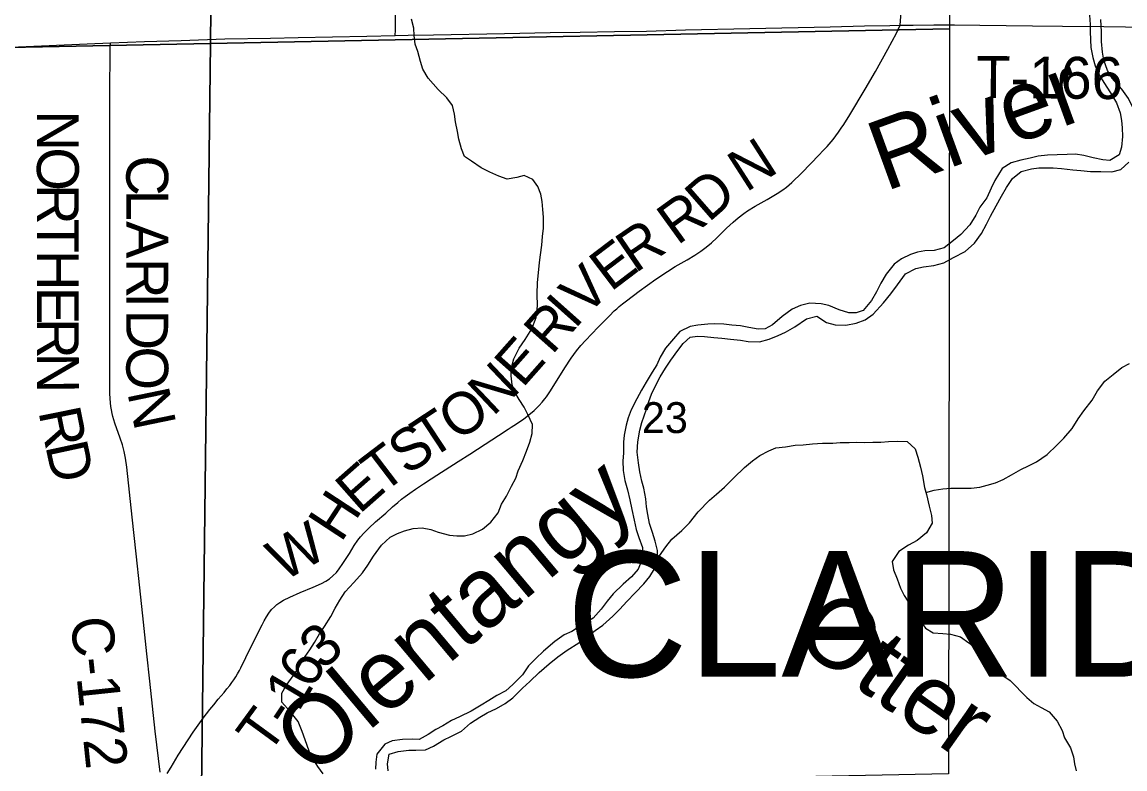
# Model space of a CAD drawing. Extents: x 0 to 45.9, y 0 to 22.
# Drawn here: x 3.224 to 4.718, y 15.719 to 16.732 of the extents above; entities that cross this region are included whole.
import ezdxf

# ---------------------------------------------------------------- set-up
doc = ezdxf.new("R2010")
doc.units = 0
for name, color, linetype in [('GM_X_County_Road', 7, 'Continuous'), ('GM_X_County_Road_Text', 7, 'Continuous'), ('GM_X_Major_River', 7, 'Continuous'), ('GM_X_Major_River_Text', 7, 'Continuous'), ('GM_X_Minor_River', 7, 'Continuous'), ('GM_X_Minor_River_Text', 7, 'Continuous'), ('GM_X_Section', 7, 'Continuous'), ('GM_X_Section_Text', 7, 'Continuous'), ('GM_X_Township_Road', 7, 'Continuous'), ('GM_X_Township_Road_Text', 7, 'Continuous'), ('GM_X_Township_Text', 7, 'Continuous')]:
    doc.layers.add(name, color=color, linetype=linetype)

msp = doc.modelspace()

# ---------------------------------------------------------------- linework, layer by layer
at = {"layer": 'GM_X_County_Road'}
for points in [[(4.4133, 16.7278), (4.4147, 16.7455)], [(3.7293, 16.7137), (3.7467, 16.7141), (3.7809, 16.7148), (3.8772, 16.7165), (3.9393, 16.7177), (3.9797, 16.7185), (4.0263, 16.7194), (4.0698, 16.7199), (4.1226, 16.7214), (4.2096, 16.7232), (4.3184, 16.7256), (4.3649, 16.7269), (4.3991, 16.7275), (4.4133, 16.7278)], [(2.9782, 16.69), (3.0044, 16.6907), (3.0727, 16.6932), (3.1659, 16.6967), (3.2187, 16.6987), (3.3118, 16.7026), (3.3433, 16.7038)], [(3.4107, 15.7149), (3.4041, 15.7704), (3.3966, 15.8383), (3.3927, 15.8754), (3.3881, 15.9186), (3.3833, 15.9649), (3.3782, 16.0112), (3.3728, 16.0606), (3.3655, 16.1286), (3.3638, 16.1408), (3.3619, 16.1499), (3.3596, 16.1588), (3.3567, 16.1677), (3.3496, 16.1882), (3.3481, 16.1928), (3.3469, 16.1972), (3.3459, 16.2015), (3.3448, 16.2063), (3.3441, 16.211), (3.3436, 16.2157), (3.3428, 16.2281), (3.3424, 16.2499), (3.3426, 16.43), (3.3427, 16.5138), (3.3426, 16.5884), (3.3425, 16.635), (3.343, 16.694), (3.3431, 16.6971), (3.3433, 16.7038)], [(3.3433, 16.7038), (3.3895, 16.7057), (3.4391, 16.7072), (3.4982, 16.7091), (3.5603, 16.7104), (3.5976, 16.7112), (3.6908, 16.7129), (3.7293, 16.7137)]]:
    msp.add_lwpolyline(points, dxfattribs=at)
at = {"layer": 'GM_X_Major_River'}
for points in [[(4.6698, 16.7416), (4.6707, 16.7287), (4.6706, 16.7192), (4.6712, 16.7078), (4.6718, 16.6976), (4.6743, 16.6839), (4.6776, 16.6728), (4.6831, 16.6595), (4.6894, 16.6499), (4.6983, 16.6361), (4.7065, 16.6227), (4.7112, 16.609), (4.713, 16.5988), (4.714, 16.5885), (4.7146, 16.5771), (4.7132, 16.5623)], [(4.7299, 16.6133), (4.7225, 16.6282), (4.7136, 16.6412), (4.7005, 16.6562), (4.6942, 16.6665), (4.6894, 16.6803), (4.6873, 16.6913), (4.686, 16.7057), (4.6862, 16.719), (4.6852, 16.7357)], [(4.7132, 16.5623), (4.7101, 16.5521), (4.6974, 16.5443), (4.688, 16.5452), (4.6747, 16.5481), (4.6619, 16.5513), (4.6509, 16.5529), (4.6395, 16.5523), (4.6262, 16.5521), (4.6129, 16.5515), (4.6004, 16.5502), (4.5893, 16.5477), (4.5768, 16.5448), (4.5638, 16.5412), (4.5516, 16.5334), (4.5415, 16.5172), (4.5364, 16.5067), (4.5309, 16.4938), (4.5213, 16.4811), (4.5158, 16.4701), (4.5077, 16.457), (4.4954, 16.4442), (4.4854, 16.436), (4.4727, 16.426), (4.4594, 16.4223), (4.4469, 16.4221), (4.4366, 16.42), (4.4271, 16.4171), (4.4152, 16.4112), (4.4053, 16.4037), (4.3941, 16.3902), (4.3871, 16.3782), (4.3812, 16.3661), (4.3746, 16.3544), (4.3631, 16.3409), (4.3535, 16.338), (4.3437, 16.3378), (4.3308, 16.3421), (4.3168, 16.3476), (4.3063, 16.3501), (4.2911, 16.351), (4.2782, 16.3478), (4.2671, 16.343), (4.2533, 16.3329), (4.2402, 16.3217), (4.2303, 16.3162), (4.2208, 16.3155), (4.2083, 16.318), (4.197, 16.3204), (4.1852, 16.3213), (4.1742, 16.3226), (4.1621, 16.3228), (4.1526, 16.3225), (4.1393, 16.3212), (4.129, 16.3191), (4.1149, 16.3124), (4.106, 16.3027), (4.0952, 16.2899), (4.0882, 16.2779), (4.0835, 16.2673), (4.0773, 16.2572), (4.0692, 16.244), (4.063, 16.2331), (4.0564, 16.221), (4.0489, 16.2063), (4.0446, 16.1954), (4.0422, 16.1855), (4.0394, 16.1719), (4.0385, 16.1625), (4.0387, 16.1477), (4.0378, 16.137), (4.038, 16.1241), (4.0404, 16.1105), (4.0437, 16.0979), (4.0469, 16.0842), (4.0498, 16.0713), (4.053, 16.0568), (4.0555, 16.0439), (4.0591, 16.0332), (4.0642, 16.0195), (4.0648, 16.0062), (4.0582, 15.9903), (4.0493, 15.9798), (4.0382, 15.9701), (4.0247, 15.9566), (4.0162, 15.9469), (4.0081, 15.936), (3.9973, 15.924), (3.9839, 15.9155), (3.9686, 15.9058), (3.9583, 15.901), (3.9453, 15.8921), (3.9299, 15.879), (3.9195, 15.8693), (3.9099, 15.8592), (3.9018, 15.8471), (3.8887, 15.8337), (3.8791, 15.8251), (3.8669, 15.8188), (3.8562, 15.8121), (3.8458, 15.8058)], [(3.8666, 15.8013), (3.8781, 15.808), (3.8885, 15.8158), (3.9015, 15.8289), (3.9115, 15.8379), (3.9242, 15.8503), (3.9377, 15.8618), (3.9495, 15.8715), (3.9622, 15.8805), (3.9779, 15.8905), (4.0001, 15.9069), (4.0105, 15.9143), (4.0239, 15.9267), (4.0335, 15.936), (4.0428, 15.9462), (4.0543, 15.9581), (4.0659, 15.9705), (4.074, 15.9803), (4.0806, 15.9908), (4.0849, 16.0036), (4.0847, 16.0154), (4.0814, 16.0283), (4.0778, 16.0401), (4.0738, 16.052), (4.0713, 16.0645), (4.0696, 16.0748), (4.0686, 16.0858), (4.0661, 16.0999), (4.0632, 16.1094), (4.0607, 16.1223), (4.0586, 16.1345), (4.0569, 16.1489), (4.0578, 16.163), (4.0607, 16.1789), (4.0635, 16.1891), (4.0698, 16.2072), (4.073, 16.2174), (4.0766, 16.2276), (4.0812, 16.2378), (4.0883, 16.2509), (4.0956, 16.263), (4.1026, 16.2735), (4.1119, 16.2867), (4.1192, 16.2964), (4.1288, 16.3046), (4.1387, 16.306), (4.1482, 16.3059), (4.1607, 16.3042), (4.1717, 16.3033), (4.1834, 16.302), (4.1971, 16.3007), (4.2073, 16.299), (4.2228, 16.2984), (4.2358, 16.3021), (4.248, 16.3072), (4.2579, 16.3116), (4.2706, 16.319), (4.2866, 16.3298), (4.3003, 16.3331), (4.3135, 16.3249), (4.3252, 16.3217), (4.3396, 16.3212), (4.3537, 16.3236), (4.3659, 16.3284), (4.3766, 16.3358), (4.3909, 16.3512), (4.4005, 16.3636), (4.4098, 16.3756), (4.4206, 16.3906), (4.4344, 16.398), (4.4451, 16.4002), (4.4587, 16.4022), (4.4724, 16.4055), (4.4854, 16.4129), (4.5015, 16.421), (4.5138, 16.4322), (4.5235, 16.4454), (4.5301, 16.4582), (4.5355, 16.4687), (4.5433, 16.4827), (4.5507, 16.4962), (4.5573, 16.5079), (4.5654, 16.5199), (4.577, 16.5296), (4.591, 16.5332), (4.6013, 16.5346), (4.6207, 16.5344), (4.632, 16.5335), (4.6472, 16.5317), (4.6582, 16.5308), (4.6711, 16.5295), (4.6851, 16.5293), (4.6999, 16.5291), (4.7121, 16.532), (4.7232, 16.5421)], [(3.8458, 15.8058), (3.8321, 15.7976), (3.8164, 15.7899), (3.8053, 15.7851), (3.7938, 15.778), (3.7843, 15.7728), (3.774, 15.7662), (3.7617, 15.7591), (3.7522, 15.7596), (3.7393, 15.7594), (3.7253, 15.7573), (3.7153, 15.7529), (3.7042, 15.7394), (3.7029, 15.7284), (3.7024, 15.7189)], [(3.7198, 15.7168), (3.7188, 15.7263), (3.7212, 15.7392), (3.7334, 15.7432), (3.7475, 15.7449), (3.7573, 15.7448), (3.7703, 15.7453), (3.7809, 15.7501), (3.7951, 15.7587), (3.8047, 15.7635), (3.8188, 15.7705), (3.8311, 15.7813), (3.8437, 15.7895), (3.854, 15.7954), (3.8666, 15.8013)]]:
    msp.add_lwpolyline(points, dxfattribs=at)
at = {"layer": 'GM_X_Minor_River'}
for points in [[(3.7739, 16.6558), (3.7668, 16.6684), (3.7636, 16.6787), (3.76, 16.692), (3.7563, 16.7019), (3.7549, 16.7137), (3.7543, 16.7236), (3.7511, 16.7362)], [(3.6317, 15.7127), (3.6242, 15.7227), (3.6176, 15.7337), (3.6128, 15.7437), (3.6073, 15.7589), (3.6033, 15.77), (3.5978, 15.7837), (3.5869, 15.7971), (3.5757, 15.8098), (3.5755, 15.8219), (3.5813, 15.8325), (3.5887, 15.8426), (3.5972, 15.8547), (3.6042, 15.8671), (3.6135, 15.881), (3.6197, 15.8908), (3.6267, 15.9024), (3.6333, 15.9126), (3.6418, 15.9261), (3.648, 15.9374), (3.6542, 15.948), (3.6616, 15.9593), (3.6732, 15.9724), (3.6847, 15.9851), (3.6921, 15.9956), (3.6998, 16.0077), (3.7107, 16.0227), (3.7222, 16.0336), (3.7321, 16.0387), (3.742, 16.0424), (3.7535, 16.0453), (3.7656, 16.0463), (3.7773, 16.0442), (3.7875, 16.0406), (3.8027, 16.0363), (3.8125, 16.0354), (3.8231, 16.0356), (3.8342, 16.0381), (3.8475, 16.0444), (3.8587, 16.0541), (3.8687, 16.0665), (3.8734, 16.0782), (3.88, 16.0891), (3.8867, 16.1027), (3.8925, 16.1136), (3.896, 16.1234), (3.9019, 16.1377), (3.907, 16.1502), (3.9118, 16.1626), (3.9146, 16.174), (3.9151, 16.1865), (3.9088, 16.1999), (3.9037, 16.2098), (3.897, 16.2205), (3.8914, 16.2301), (3.8878, 16.2404), (3.8864, 16.2525), (3.8866, 16.2639), (3.8898, 16.2756), (3.8972, 16.2899), (3.9053, 16.3016), (3.9142, 16.3163), (3.9201, 16.3317), (3.9222, 16.3473), (3.9217, 16.3632), (3.9219, 16.3788), (3.9232, 16.392), (3.9249, 16.406), (3.9262, 16.4166), (3.9279, 16.4295), (3.9288, 16.4413), (3.9301, 16.4526), (3.9299, 16.4674), (3.9293, 16.4777), (3.9283, 16.4887), (3.9266, 16.4986), (3.9225, 16.5093), (3.9158, 16.5188), (3.9038, 16.5239), (3.8942, 16.5214), (3.8809, 16.5189), (3.8696, 16.5229), (3.8572, 16.5287), (3.8455, 16.5346), (3.8327, 16.5435), (3.8229, 16.55), (3.8189, 16.56), (3.8156, 16.5733), (3.8135, 16.5839), (3.811, 16.5969), (3.8097, 16.6071), (3.8068, 16.6189), (3.7993, 16.6293), (3.7873, 16.6404), (3.7739, 16.6558)], [(4.448, 16.0944), (4.4592, 16.0972), (4.4713, 16.099), (4.482, 16.1), (4.4933, 16.1002), (4.5093, 16.1), (4.5211, 16.1013), (4.5313, 16.1042), (4.5424, 16.1075), (4.5527, 16.1119), (4.5642, 16.1182), (4.5768, 16.1252), (4.5871, 16.1304), (4.5982, 16.1359), (4.6123, 16.1456), (4.6254, 16.1583), (4.635, 16.1677), (4.6462, 16.1812), (4.6544, 16.194), (4.6621, 16.2049), (4.6733, 16.2195), (4.6807, 16.232), (4.6907, 16.2451), (4.7019, 16.2544), (4.7137, 16.2638), (4.7241, 16.2693)], [(4.0849, 16.0044), (4.0872, 16.0085), (4.0958, 16.0206), (4.1039, 16.0311), (4.1177, 16.0426), (4.1281, 16.0531), (4.1397, 16.0681), (4.155, 16.0839), (4.1646, 16.0921), (4.1754, 16.1014), (4.1881, 16.1142), (4.2023, 16.128), (4.2131, 16.1373), (4.2234, 16.1444), (4.2353, 16.1507), (4.2448, 16.1547), (4.2581, 16.1561), (4.271, 16.1582), (4.2817, 16.1588), (4.2946, 16.1601), (4.3082, 16.1611), (4.3219, 16.1613), (4.3322, 16.1619), (4.3443, 16.1621), (4.3546, 16.1624), (4.3648, 16.1622), (4.3762, 16.1625), (4.3872, 16.1623), (4.3974, 16.1633), (4.41, 16.1639), (4.4229, 16.1633), (4.4337, 16.1533), (4.437, 16.1423), (4.441, 16.1286), (4.4435, 16.1168), (4.4463, 16.1012), (4.4488, 16.0913), (4.4524, 16.0757), (4.4557, 16.0631), (4.4567, 16.0525), (4.4489, 16.0397), (4.4362, 16.0292), (4.4244, 16.023), (4.4117, 16.014), (4.4024, 16.0005), (4.4042, 15.9895), (4.409, 15.9773), (4.4137, 15.9643), (4.4189, 15.9544), (4.4338, 15.9314), (4.4408, 15.9199), (4.4475, 15.9104), (4.458, 15.9038), (4.4709, 15.9032), (4.4815, 15.9019), (4.4948, 15.8983), (4.5064, 15.8902), (4.5181, 15.8802), (4.5289, 15.866), (4.5394, 15.856), (4.5495, 15.8479), (4.5623, 15.8394), (4.5847, 15.8163), (4.5945, 15.8082), (4.6043, 15.8028), (4.6152, 15.7966), (4.626, 15.7843), (4.6327, 15.7717), (4.636, 15.7614), (4.6441, 15.748), (4.6481, 15.7358), (4.6495, 15.7263), (4.6517, 15.7168)]]:
    msp.add_lwpolyline(points, dxfattribs=at)
at = {"layer": 'GM_X_Section'}
for points in [[(3.4888, 17.7149), (4.477, 17.7336), (4.4801, 16.7228), (3.479, 16.7029)], [(2.4867, 17.6967), (3.4888, 17.7149), (3.479, 16.7029), (2.4763, 16.6833)], [(3.479, 16.7029), (4.4801, 16.7228), (4.4787, 15.7127), (3.467, 15.6926)], [(3.479, 16.7029), (3.467, 15.6926), (2.4689, 15.6797), (2.4763, 16.6833)]]:
    msp.add_lwpolyline(points, close=True, dxfattribs=at)
at = {"layer": 'GM_X_Township_Road'}
for points in [[(3.7293, 16.7137), (3.7294, 16.7209), (3.7294, 16.724), (3.7294, 16.7613), (3.7293, 16.8016), (3.7299, 16.8638), (3.7302, 16.9259), (3.7302, 16.9974), (3.7299, 17.0471), (3.7297, 17.0875), (3.7299, 17.1279), (3.7299, 17.1714), (3.7296, 17.2087), (3.7298, 17.2304), (3.7301, 17.2646), (3.7305, 17.3205), (3.7309, 17.3734), (3.7319, 17.5101), (3.7325, 17.5753), (3.7326, 17.6219), (3.7331, 17.6717), (3.733, 17.6996), (3.7332, 17.7248)], [(3.9318, 16.2212), (3.9341, 16.2241), (3.9394, 16.2319), (3.9591, 16.2634), (3.9676, 16.2764), (3.9749, 16.2863), (3.9809, 16.2934), (3.9871, 16.3002), (4.0042, 16.3182), (4.0193, 16.3339), (4.0259, 16.3403), (4.0293, 16.3434), (4.0328, 16.3465), (4.0371, 16.35), (4.0425, 16.3543), (4.0598, 16.3674), (4.0825, 16.3836), (4.0979, 16.394), (4.1085, 16.4006), (4.1246, 16.4098), (4.1353, 16.4162), (4.1391, 16.4186), (4.1431, 16.4213), (4.1506, 16.4269), (4.1578, 16.4329), (4.1647, 16.4393), (4.1779, 16.4524), (4.1869, 16.4609), (4.194, 16.4668), (4.2013, 16.4725), (4.2064, 16.4759), (4.217, 16.4824), (4.2332, 16.4915), (4.2467, 16.4994), (4.2545, 16.5045), (4.2595, 16.5083), (4.2665, 16.5145), (4.2799, 16.5275), (4.3037, 16.5521), (4.3087, 16.5574), (4.3143, 16.5635), (4.3224, 16.573), (4.326, 16.5776), (4.3299, 16.5829), (4.3335, 16.588), (4.337, 16.5932), (4.3452, 16.6064), (4.3658, 16.6409), (4.38, 16.6652), (4.3964, 16.6952), (4.4083, 16.7171), (4.4106, 16.7219), (4.4133, 16.7278)], [(4.4133, 16.7278), (4.431, 16.728), (4.459, 16.7284), (4.487, 16.7285), (4.5211, 16.7279), (4.5926, 16.7269), (4.633, 16.7265), (4.689, 16.726), (4.8071, 16.7244), (4.8475, 16.7243), (4.8755, 16.7243), (4.9003, 16.7241), (4.9314, 16.7233), (4.9656, 16.7224), (5.0029, 16.7213), (5.037, 16.72), (5.0743, 16.7181), (5.096, 16.7169), (5.1332, 16.7151), (5.2233, 16.7105), (5.2313, 16.7102)], [(3.8864, 16.1829), (3.8899, 16.1851), (3.9028, 16.1938), (3.9103, 16.1994), (3.9175, 16.2055), (3.9242, 16.212), (3.9283, 16.2167), (3.9318, 16.2212)], [(3.4204, 15.7133), (3.4256, 15.7219), (3.4351, 15.738), (3.4556, 15.7691), (3.4645, 15.7818), (3.4678, 15.7863), (3.4738, 15.7942), (3.478, 15.7998), (3.4834, 15.8064), (3.4895, 15.8138), (3.4973, 15.8231), (3.5011, 15.8278), (3.505, 15.8325), (3.5077, 15.8364), (3.5105, 15.8403), (3.5131, 15.8442), (3.5156, 15.8483), (3.5182, 15.8529), (3.5201, 15.8565), (3.5267, 15.8704), (3.5403, 15.8982), (3.5488, 15.915), (3.5517, 15.9203), (3.5547, 15.9255), (3.558, 15.9306), (3.5618, 15.9354), (3.5655, 15.9394), (3.5689, 15.9422), (3.5729, 15.9452), (3.5779, 15.9482), (3.5864, 15.9525), (3.6006, 15.9588), (3.6181, 15.966), (3.6295, 15.9708), (3.6353, 15.9739), (3.6401, 15.9771), (3.6448, 15.9811), (3.6495, 15.9858), (3.6535, 15.9905), (3.6584, 15.9979), (3.663, 16.0047), (3.6673, 16.0116), (3.6737, 16.0223), (3.6785, 16.0294), (3.6823, 16.034), (3.6868, 16.0391), (3.6935, 16.0458), (3.7023, 16.0543), (3.7164, 16.0664), (3.7256, 16.0747), (3.7326, 16.0808), (3.7379, 16.085), (3.7425, 16.0886), (3.7491, 16.0934), (3.7567, 16.0988), (3.762, 16.1022), (3.7677, 16.1058), (3.778, 16.1128), (3.7858, 16.1178), (3.8146, 16.1362), (3.8302, 16.1463), (3.8511, 16.1598), (3.8693, 16.1716), (3.8821, 16.1801), (3.8864, 16.1829)]]:
    msp.add_lwpolyline(points, dxfattribs=at)

# ---------------------------------------------------------------- texts
at = {"layer": 'GM_X_County_Road_Text'}
for s, height, rotation, p in [('N', 0.0568, 270, (3.2438, 16.6122)), ('O', 0.0568, 269.9981, (3.2438, 16.5622)), ('C', 0.0568, 270, (3.3649, 16.5514)), ('R', 0.0568, 269.9991, (3.2438, 16.5122)), ('L', 0.0568, 269.9985, (3.3649, 16.5047)), ('T', 0.0568, 269.9985, (3.2438, 16.4655)), ('A', 0.0568, 270, (3.3649, 16.4622)), ('H', 0.0568, 270, (3.2438, 16.423)), ('R', 0.0568, 269.9991, (3.3649, 16.4122)), ('E', 0.0568, 269.9985, (3.2438, 16.373)), ('I', 0.0568, 270, (3.3649, 16.3655)), ('D', 0.0568, 269.9981, (3.3649, 16.3422)), ('R', 0.0568, 270.0322, (3.2438, 16.3305)), ('O', 0.0568, 270.0488, (3.3649, 16.2922)), ('N', 0.0568, 270.1952, (3.2438, 16.2837)), ('N', 0.0568, 281.6646, (3.3662, 16.2297)), ('R', 0.0568, 281.4365, (3.2457, 16.2041)), ('D', 0.0568, 282.192, (3.2551, 16.1575)), ('C-172', 0.05682, 276.0509, (3.2892, 15.9233))]:
    msp.add_text(s, height=height, rotation=rotation, dxfattribs=at).set_placement(p)
at = {"layer": 'GM_X_Major_River_Text'}
for s, rotation, p in [('River', 20.0098, (4.3929, 16.502)), ('Olentangy', 40.0104, (3.6172, 15.7064))]:
    msp.add_text(s, height=0.09471, rotation=rotation, dxfattribs=at).set_placement(p)
at = {"layer": 'GM_X_Minor_River_Text'}
msp.add_text('Otter', height=0.09471, rotation=324.81, dxfattribs=at).set_placement((4.2657, 15.8918))
at = {"layer": 'GM_X_Section_Text'}
msp.add_text('23', height=0.04186, rotation=0, dxfattribs=at).set_placement((4.0634, 16.1748))
at = {"layer": 'GM_X_Township_Road_Text'}
for s, height, rotation, p in [('T-166', 0.05682, 359.4474, (4.5162, 16.6294)), ('N', 0.0568, 32.645, (4.2045, 16.5005)), ('D', 0.0568, 41.14, (4.1537, 16.4594)), ('R', 0.0568, 35.8561, (4.1114, 16.4285)), ('R', 0.0568, 34.4024, (4.0543, 16.3907)), ('E', 0.0568, 37.2333, (4.0211, 16.3655)), ('V', 0.0568, 45.0567, (3.9873, 16.3314)), ('I', 0.0568, 48.3302, (3.9724, 16.3146)), ('R', 0.0568, 48.4822, (3.9415, 16.2797)), ('E', 0.0568, 48.5033, (3.9017, 16.2348)), ('N', 0.0568, 43.3852, (3.8615, 16.1964)), ('O', 0.0568, 34.7438, (3.8132, 16.1621)), ('T', 0.0568, 33.3406, (3.7764, 16.1378)), ('S', 0.0568, 33.8047, (3.7447, 16.1166)), ('T', 0.0568, 37.2856, (3.7116, 16.0914)), ('E', 0.0568, 41.4218, (3.6806, 16.0639)), ('H', 0.0568, 56.7287, (3.6558, 16.0252)), ('W', 0.0568, 29.8135, (3.5776, 15.9726)), ('3', 0.0568, 41.5756, (3.6311, 15.8521)), ('6', 0.0568, 59.1139, (3.616, 15.8256)), ('1', 0.0568, 59.3186, (3.5982, 15.7956)), ('T', 0.0568, 53.8141, (3.5568, 15.7369)), ('-', 0.0568, 56.2348, (3.5834, 15.7734))]:
    msp.add_text(s, height=height, rotation=rotation, dxfattribs=at).set_placement(p)
at = {"layer": 'GM_X_Township_Text'}
msp.add_text('CLARIDON', height=0.17045, rotation=0, dxfattribs=at).set_placement((3.961, 15.8443))

doc.saveas('drawing.dxf')
